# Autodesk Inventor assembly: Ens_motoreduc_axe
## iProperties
Shininess: 64.0
Length Units: 11269
Angle Units: 11279
Time Units: 11290
Mass Units: 11283
Length Display Precision: 3
Angle Display Precision: 2
Compacted: True
Created: 2008-03
Part Number: Ens_motoreduc_axe
Document SubType Name: Assembly
Designer: Pascal
Density: 0.0
Volumn: 0.0
Area: 0.0
PropertySet Name: Model Information
Control State: 0
Master: False
Checked Out: False
Author: Pascal
